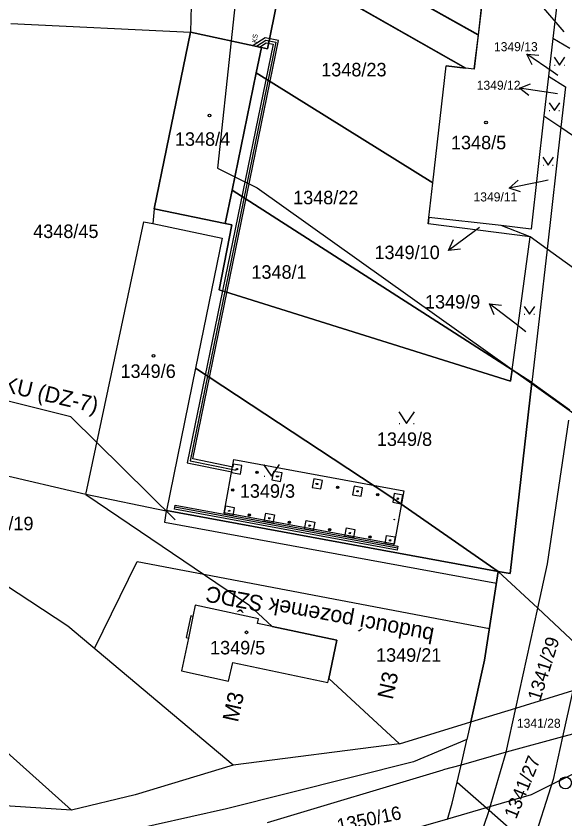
# Model space of a CAD drawing. Extents: x -735036 to -734743, y -1144813 to -1144181.
# Drawn here: x -734915.4 to -734846.3, y -1144707.5 to -1144606.3 of the extents above; entities that cross this region are included whole.
import ezdxf

# ---------------------------------------------------------------- set-up
doc = ezdxf.new("R2010")
doc.units = 0
for name, color, linetype in [('A3_ODVODŇOVACÍ ŽLAB', 7, 'Continuous'), ('A3_SIT_OBJEKT_N', 7, 'Continuous'), ('A3_SIT_OBJEKTY_N01', 7, 'Continuous'), ('BPEJ', 7, 'Continuous'), ('CKEL_VEDENI_NN_PODZ_N', 7, 'Continuous'), ('CKTEXTY_MALE', 7, 'Continuous'), ('hranice pl. určené SŽDC', 7, 'Continuous'), ('Katastr_HRANICE DRÁHY', 7, 'Continuous'), ('Katastr_Hranice parcel', 7, 'Continuous'), ('Katastr_Parcelní čísla', 7, 'Continuous'), ('Katastr_pozemek SŽDC_šrafy', 7, 'Continuous'), ('Katastr_pozemek_ČD_šrafy', 7, 'Continuous'), ('Katastr_Slučkované čáry', 7, 'Continuous'), ('Katastr_Značky kultur', 7, 'Continuous'), ('ZÁBORY_dočasné', 7, 'Continuous'), ('ZÁBORY_dočasné_šrafy', 7, 'Continuous')]:
    doc.layers.add(name, color=color, linetype=linetype)

msp = doc.modelspace()

# ---------------------------------------------------------------- linework, layer by layer
at = {"layer": 'A3_ODVODŇOVACÍ ŽLAB'}
msp.add_line((-734867.33, -1144673.4), (-734895.36, -1144668.25), dxfattribs=at)
at = {"layer": 'A3_SIT_OBJEKT_N'}
for p, q in [((-734895.42, -1144668.49), (-734895.31, -1144668)), ((-734867.38, -1144673.65), (-734895.42, -1144668.49)), ((-734895.31, -1144668), (-734867.29, -1144673.15)), ((-734867.29, -1144673.15), (-734867.38, -1144673.65))]:
    msp.add_line(p, q, dxfattribs=at)
at = {"layer": 'A3_SIT_OBJEKTY_N01'}
for p, q in [((-734887.65, -1144663.5), (-734887.62, -1144663.35)), ((-734887.5, -1144663.53), (-734887.65, -1144663.5)), ((-734887.62, -1144663.35), (-734887.48, -1144663.38)), ((-734887.48, -1144663.38), (-734887.5, -1144663.53)), ((-734885.06, -1144663.88), (-734885.05, -1144663.83)), ((-734885, -1144663.9), (-734885.06, -1144663.88)), ((-734885.05, -1144663.83), (-734884.99, -1144663.84)), ((-734884.99, -1144663.84), (-734885, -1144663.9)), ((-734882.59, -1144664.43), (-734882.56, -1144664.28)), ((-734882.44, -1144664.46), (-734882.59, -1144664.43)), ((-734882.56, -1144664.28), (-734882.31, -1144664.33)), ((-734882.43, -1144664.41), (-734882.44, -1144664.46)), ((-734882.33, -1144664.43), (-734882.43, -1144664.41)), ((-734882.31, -1144664.33), (-734882.33, -1144664.43)), ((-734877.61, -1144665.29), (-734877.59, -1144665.2)), ((-734877.51, -1144665.31), (-734877.61, -1144665.29)), ((-734877.59, -1144665.2), (-734877.35, -1144665.24)), ((-734877.52, -1144665.36), (-734877.51, -1144665.31)), ((-734877.37, -1144665.39), (-734877.52, -1144665.36)), ((-734877.35, -1144665.24), (-734877.37, -1144665.39)), ((-734874.93, -1144665.75), (-734874.92, -1144665.69)), ((-734874.92, -1144665.69), (-734874.86, -1144665.7)), ((-734874.86, -1144665.7), (-734874.87, -1144665.76)), ((-734888.13, -1144666.09), (-734888.12, -1144666.03)), ((-734888.07, -1144666.1), (-734888.13, -1144666.09)), ((-734888.12, -1144666.03), (-734888.06, -1144666.04)), ((-734888.06, -1144666.04), (-734888.07, -1144666.1)), ((-734874.87, -1144665.76), (-734874.93, -1144665.75)), ((-734872.46, -1144666.29), (-734872.43, -1144666.15)), ((-734872.31, -1144666.32), (-734872.46, -1144666.29)), ((-734872.43, -1144666.15), (-734872.28, -1144666.17)), ((-734872.28, -1144666.17), (-734872.31, -1144666.32)), ((-734869.86, -1144666.68), (-734869.85, -1144666.62)), ((-734869.8, -1144666.69), (-734869.86, -1144666.68)), ((-734869.85, -1144666.62), (-734869.79, -1144666.63)), ((-734869.79, -1144666.63), (-734869.8, -1144666.69)), ((-734867.39, -1144667.22), (-734867.36, -1144667.08)), ((-734867.24, -1144667.25), (-734867.39, -1144667.22)), ((-734867.36, -1144667.08), (-734867.22, -1144667.1)), ((-734867.22, -1144667.1), (-734867.24, -1144667.25)), ((-734888.62, -1144668.76), (-734888.59, -1144668.61)), ((-734888.59, -1144668.61), (-734888.44, -1144668.64)), ((-734888.44, -1144668.64), (-734888.47, -1144668.79)), ((-734888.47, -1144668.79), (-734888.62, -1144668.76)), ((-734886.04, -1144669.24), (-734886.03, -1144669.18)), ((-734885.98, -1144669.25), (-734886.04, -1144669.24)), ((-734886.03, -1144669.18), (-734885.97, -1144669.19)), ((-734885.97, -1144669.19), (-734885.98, -1144669.25)), ((-734883.55, -1144669.69), (-734883.53, -1144669.55)), ((-734883.41, -1144669.72), (-734883.55, -1144669.69)), ((-734883.53, -1144669.55), (-734883.38, -1144669.57)), ((-734883.38, -1144669.57), (-734883.41, -1144669.72)), ((-734880.98, -1144670.17), (-734880.97, -1144670.11)), ((-734880.92, -1144670.18), (-734880.98, -1144670.17)), ((-734880.97, -1144670.11), (-734880.91, -1144670.12)), ((-734880.91, -1144670.12), (-734880.92, -1144670.18)), ((-734878.49, -1144670.62), (-734878.46, -1144670.48)), ((-734878.34, -1144670.65), (-734878.49, -1144670.62)), ((-734878.46, -1144670.48), (-734878.31, -1144670.5)), ((-734878.31, -1144670.5), (-734878.34, -1144670.65)), ((-734867.78, -1144669.83), (-734867.77, -1144669.77)), ((-734867.72, -1144669.84), (-734867.78, -1144669.83)), ((-734867.77, -1144669.77), (-734867.71, -1144669.78)), ((-734867.71, -1144669.78), (-734867.72, -1144669.84)), ((-734875.91, -1144671.1), (-734875.9, -1144671.04)), ((-734875.85, -1144671.11), (-734875.91, -1144671.1)), ((-734875.9, -1144671.04), (-734875.84, -1144671.05)), ((-734875.84, -1144671.05), (-734875.85, -1144671.11)), ((-734873.42, -1144671.56), (-734873.4, -1144671.41)), ((-734873.28, -1144671.58), (-734873.42, -1144671.56)), ((-734873.4, -1144671.41), (-734873.25, -1144671.43)), ((-734873.25, -1144671.43), (-734873.28, -1144671.58)), ((-734870.85, -1144672.03), (-734870.84, -1144671.97)), ((-734870.79, -1144672.04), (-734870.85, -1144672.03)), ((-734870.84, -1144671.97), (-734870.78, -1144671.98)), ((-734870.78, -1144671.98), (-734870.79, -1144672.04)), ((-734868.36, -1144672.49), (-734868.33, -1144672.34)), ((-734868.21, -1144672.51), (-734868.36, -1144672.49)), ((-734868.33, -1144672.34), (-734868.18, -1144672.37)), ((-734868.18, -1144672.37), (-734868.21, -1144672.51))]:
    msp.add_line(p, q, dxfattribs=at)
for points in [[(-734888.19, -1144663.78), (-734888.21, -1144663.88), (-734887.12, -1144664.08), (-734886.92, -1144663), (-734888.01, -1144662.8), (-734888.08, -1144663.19), (-734893.11, -1144662.16), (-734882.3, -1144609.42), (-734883.98, -1144609.08), (-734885.53, -1144610.07), (-734884.7, -1144610.25), (-734883.87, -1144609.71), (-734883.01, -1144609.89), (-734893.81, -1144662.63)], [(-734889.17, -1144668.97), (-734887.93, -1144662.23), (-734866.54, -1144666.16), (-734867.77, -1144672.9)], [(-734882.94, -1144663.73), (-734883.14, -1144664.81), (-734882.06, -1144665.01), (-734881.86, -1144663.93)], [(-734877.88, -1144664.66), (-734878.07, -1144665.74), (-734876.99, -1144665.94), (-734876.79, -1144664.86)], [(-734872.81, -1144665.59), (-734873.01, -1144666.67), (-734871.93, -1144666.87), (-734871.73, -1144665.79)], [(-734867.75, -1144666.52), (-734867.94, -1144667.61), (-734866.86, -1144667.8), (-734866.66, -1144666.72)], [(-734889.17, -1144669.13), (-734888.97, -1144668.06), (-734887.89, -1144668.26), (-734888.09, -1144669.33)], [(-734884.11, -1144670.06), (-734883.91, -1144668.99), (-734882.83, -1144669.19), (-734883.02, -1144670.26)], [(-734879.04, -1144670.99), (-734878.84, -1144669.92), (-734877.76, -1144670.12), (-734877.96, -1144671.19)], [(-734873.98, -1144671.93), (-734873.78, -1144670.85), (-734872.7, -1144671.05), (-734872.89, -1144672.12)], [(-734868.91, -1144672.86), (-734868.71, -1144671.79), (-734867.63, -1144671.98), (-734867.83, -1144673.06)]]:
    msp.add_lwpolyline(points, close=True, dxfattribs=at)
for centre in [(-734885.02, -1144663.86), (-734874.89, -1144665.72), (-734888.09, -1144666.06), (-734869.83, -1144666.65), (-734886.01, -1144669.21), (-734880.94, -1144670.14), (-734875.88, -1144671.07), (-734870.81, -1144672)]:
    msp.add_circle(centre, 0.15, dxfattribs=at)
at = {"layer": 'BPEJ'}
for points in [[(-734886.95, -1144596.85), (-734888.29, -1144609.47), (-734890, -1144625.5), (-734887.82, -1144626.59), (-734885, -1144628), (-734852.91, -1144650.88), (-734852.15, -1144651.42), (-734850.43, -1144652.65), (-734834.73, -1144663.85), (-734834.99, -1144666), (-734826.29, -1144672.48), (-734825.67, -1144670.31), (-734820.68, -1144673.87), (-734820.5, -1144674), (-734820.82, -1144674.78), (-734818.52, -1144675.9), (-734816.23, -1144677.02), (-734810.97, -1144679.57), (-734807.09, -1144681.45), (-734806.63, -1144681.68), (-734805.5, -1144680.5), (-734802.5, -1144683.25), (-734799.5, -1144686)], [(-734875.41, -1144811.46), (-734872.9, -1144805.78), (-734867.89, -1144794.43), (-734854.34, -1144763.72), (-734850.2, -1144754.32), (-734842.33, -1144736.48), (-734836.55, -1144723.38), (-734836.47, -1144723.21), (-734828.55, -1144705.26), (-734828.47, -1144705.07), (-734837.14, -1144702.69), (-734834.01, -1144696), (-734841.2, -1144699.67), (-734841.55, -1144701.48), (-734843.42, -1144700.96), (-734850.5, -1144704.5), (-734856.16, -1144706.13), (-734861.05, -1144707.56), (-734878.02, -1144712.44), (-734888.06, -1144715.34), (-734896.33, -1144716.95), (-734914.06, -1144720.39), (-734915.89, -1144720.74)]]:
    msp.add_lwpolyline(points, dxfattribs=at)
at = {"layer": 'CKEL_VEDENI_NN_PODZ_N'}
msp.add_lwpolyline([(-734885.11, -1144610.16), (-734883.92, -1144609.39), (-734882.65, -1144609.66), (-734893.46, -1144662.4), (-734887.67, -1144663.58)], dxfattribs=at)
at = {"layer": 'hranice pl. určené SŽDC'}
for p, q in [((-734905.48, -1144686.06), (-734900.12, -1144675.07)), ((-734900.12, -1144675.07), (-734855.78, -1144683.52))]:
    msp.add_line(p, q, dxfattribs=at)
at = {"layer": 'Katastr_HRANICE DRÁHY'}
for p, q in [((-734906.57, -1144666.66), (-734899.28, -1144632.27)), ((-734906.57, -1144666.66), (-734930.18, -1144661.14)), ((-734867.09, -1144698.06), (-734888.03, -1144700.76))]:
    msp.add_line(p, q, dxfattribs=at)
for points in [[(-734893.32, -1144605), (-734893.39, -1144608.37)], [(-734896.4, -1144623.07), (-734893.39, -1144608.37)], [(-734846.19, -1144615.27), (-734846.77, -1144620.37)], [(-734846.77, -1144620.37), (-734848.51, -1144635.73)], [(-734897.96, -1144630.65), (-734896.4, -1144623.07)], [(-734897.96, -1144630.65), (-734898.12, -1144632.51)], [(-734899.28, -1144632.27), (-734898.12, -1144632.51)], [(-734848.51, -1144635.73), (-734850.42, -1144652.54)], [(-734850.42, -1144652.54), (-734853.15, -1144676.61)], [(-734908.82, -1144683.24), (-734932.55, -1144667.65)], [(-734854.65, -1144676.33), (-734856.41, -1144687.5)], [(-734853.15, -1144676.61), (-734854.65, -1144676.33)], [(-734888.03, -1144700.76), (-734908.82, -1144683.24)], [(-734856.41, -1144687.5), (-734858.12, -1144695.3)], [(-734867.09, -1144698.06), (-734858.12, -1144695.3)]]:
    msp.add_lwpolyline(points, dxfattribs=at)
at = {"layer": 'Katastr_Hranice parcel'}
for points in [[(-734857.17, -1144608.74), (-734880.66, -1144595.58)], [(-734883.7, -1144610.47), (-734881.55, -1144599.93)], [(-734881.55, -1144599.93), (-734858.79, -1144612.91)], [(-734846.8, -1144600.6), (-734847.79, -1144609.19)], [(-734856.63, -1144604.15), (-734857.17, -1144608.74)], [(-734916.03, -1144607.28), (-734893.39, -1144608.37)], [(-734893.39, -1144608.37), (-734884.47, -1144610.3)], [(-734857.17, -1144608.74), (-734857.68, -1144613.04)], [(-734847.79, -1144609.19), (-734848.33, -1144613.91)], [(-734845.64, -1144610.44), (-734847.79, -1144609.19)], [(-734885.13, -1144613.52), (-734884.47, -1144610.3)], [(-734884.47, -1144610.3), (-734883.7, -1144610.47)], [(-734862.9, -1144627.38), (-734861.22, -1144612.64)], [(-734858.79, -1144612.91), (-734861.22, -1144612.64)], [(-734857.68, -1144613.04), (-734858.79, -1144612.91)], [(-734888.17, -1144628.27), (-734885.13, -1144613.52)], [(-734885.13, -1144613.52), (-734862.9, -1144627.38)], [(-734848.33, -1144613.91), (-734848.9, -1144618.91)], [(-734848.33, -1144613.91), (-734846.19, -1144615.27)], [(-734848.9, -1144618.91), (-734850.53, -1144633.19)], [(-734848.9, -1144618.91), (-734846.77, -1144620.37)], [(-734846.77, -1144620.37), (-734841.89, -1144623.71)], [(-734889.04, -1144632.49), (-734888.17, -1144628.27)], [(-734888.17, -1144628.27), (-734852.92, -1144650.93)], [(-734863.4, -1144631.72), (-734862.9, -1144627.38)], [(-734889.04, -1144632.49), (-734897.96, -1144630.65)], [(-734863.4, -1144631.72), (-734863.49, -1144632.52)], [(-734854.28, -1144632.76), (-734863.4, -1144631.72)], [(-734898.12, -1144632.51), (-734889.41, -1144634.32)], [(-734889.81, -1144640.87), (-734888.21, -1144632.66)], [(-734888.21, -1144632.66), (-734889.04, -1144632.49)], [(-734850.65, -1144634.19), (-734863.49, -1144632.52)], [(-734850.53, -1144633.19), (-734854.28, -1144632.76)], [(-734850.65, -1144634.19), (-734854.28, -1144632.76)], [(-734889.41, -1144634.32), (-734892.76, -1144650.74)], [(-734852.92, -1144650.93), (-734850.65, -1144634.19)], [(-734848.51, -1144635.73), (-734850.65, -1144634.19)], [(-734843.69, -1144639.2), (-734848.51, -1144635.73)], [(-734853.11, -1144652.34), (-734889.81, -1144640.87)], [(-734892.76, -1144650.74), (-734896.42, -1144668.65)], [(-734892.76, -1144650.74), (-734868.44, -1144666.76)], [(-734852.92, -1144650.93), (-734853.11, -1144652.34)], [(-734852.92, -1144650.93), (-734850.42, -1144652.54)], [(-734850.42, -1144652.54), (-734845.63, -1144655.97)], [(-734896.45, -1144668.76), (-734906.57, -1144666.66)], [(-734906.57, -1144666.66), (-734886.07, -1144680.55)], [(-734854.65, -1144676.33), (-734868.44, -1144666.76)], [(-734896.42, -1144668.65), (-734896.45, -1144668.76)], [(-734854.65, -1144676.33), (-734896.42, -1144668.65)], [(-734849.69, -1144680.98), (-734854.65, -1144676.33)], [(-734892.81, -1144680.6), (-734893.1, -1144682)], [(-734884.85, -1144682.29), (-734892.81, -1144680.6)], [(-734886.07, -1144680.55), (-734883.11, -1144683.28)], [(-734844.19, -1144686.14), (-734849.69, -1144680.98)], [(-734908.39, -1144706.42), (-734935.61, -1144682)], [(-734893.37, -1144681.94), (-734893.96, -1144684.67)], [(-734893.1, -1144682), (-734893.37, -1144681.94)], [(-734884.98, -1144682.88), (-734884.85, -1144682.29)], [(-734883.11, -1144683.28), (-734884.98, -1144682.88)], [(-734874.98, -1144685.01), (-734883.11, -1144683.28)], [(-734893.67, -1144684.73), (-734894.55, -1144688.88)], [(-734893.96, -1144684.67), (-734893.67, -1144684.73)], [(-734876, -1144689.84), (-734874.98, -1144685.01)], [(-734888.61, -1144690.15), (-734888.09, -1144687.8)], [(-734888.09, -1144687.8), (-734876.11, -1144690.34)], [(-734894.55, -1144688.88), (-734888.61, -1144690.15)], [(-734876.11, -1144690.34), (-734876, -1144689.84)], [(-734876, -1144689.84), (-734867.09, -1144698.06)], [(-734852.46, -1144693.56), (-734845.28, -1144691.36)], [(-734858.12, -1144695.3), (-734852.46, -1144693.56)], [(-734858.12, -1144695.3), (-734858.6, -1144697.51)], [(-734840.41, -1144695.55), (-734846.56, -1144697.19)], [(-734858.6, -1144697.51), (-734865.34, -1144700.35)], [(-734859.34, -1144700.73), (-734858.65, -1144697.78)], [(-734858.65, -1144697.78), (-734858.6, -1144697.51)], [(-734846.56, -1144697.19), (-734853.68, -1144699.09)], [(-734853.68, -1144699.09), (-734859.34, -1144700.73)], [(-734888.03, -1144700.76), (-734900.37, -1144704.49)], [(-734865.34, -1144700.35), (-734888.87, -1144706.25)], [(-734859.34, -1144700.73), (-734861.61, -1144701.35)], [(-734859.84, -1144702.9), (-734859.34, -1144700.73)], [(-734883.72, -1144707.99), (-734861.61, -1144701.35)], [(-734860.46, -1144705.55), (-734859.84, -1144702.9)], [(-734859.84, -1144702.9), (-734855.82, -1144706.43)], [(-734908.39, -1144706.42), (-734927.72, -1144705.17)], [(-734900.37, -1144704.49), (-734908.39, -1144706.42)], [(-734861.06, -1144707.58), (-734860.46, -1144705.55)], [(-734888.87, -1144706.25), (-734902.35, -1144709.26)], [(-734855.82, -1144706.43), (-734850.48, -1144711.13)]]:
    msp.add_lwpolyline(points, dxfattribs=at)
at = {"layer": 'Katastr_Parcelní čísla'}
for p, q in [((-734846.36, -1144608.35), (-734847.12, -1144607.47)), ((-734850.4, -1144612.5), (-734851.04, -1144611.14)), ((-734847.15, -1144613.85), (-734847.76, -1144613.43)), ((-734850.82, -1144616.36), (-734852, -1144615.43)), ((-734847.22, -1144616.14), (-734848.04, -1144616.02)), ((-734848.37, -1144627.04), (-734849.36, -1144627.24)), ((-734851.86, -1144628.51), (-734853.28, -1144628.03)), ((-734857.03, -1144632.99), (-734857.7, -1144633.49)), ((-734859.42, -1144635.71), (-734860.91, -1144635.88)), ((-734855.17, -1144643.99), (-734855.74, -1144642.6)), ((-734851.17, -1144646.14), (-734852.58, -1144645.05))]:
    msp.add_line(p, q, dxfattribs=at)
for points in [[(-734847.12, -1144607.47), (-734849.73, -1144604.44), (-734848.32, -1144604.94)], [(-734847.76, -1144613.43), (-734851.04, -1144611.14), (-734849.55, -1144611.27)], [(-734848.04, -1144616.02), (-734852, -1144615.43), (-734850.6, -1144614.88)], [(-734849.36, -1144627.24), (-734853.28, -1144628.03), (-734852.15, -1144627.04)], [(-734857.7, -1144633.49), (-734860.91, -1144635.88), (-734860.31, -1144634.5)], [(-734852.58, -1144645.05), (-734855.74, -1144642.6), (-734854.25, -1144642.8)]]:
    msp.add_lwpolyline(points, dxfattribs=at)
at = {"layer": 'Katastr_pozemek SŽDC_šrafy'}
for points in [[(-734879.81, -1144591.4), (-734880.65, -1144595.54), (-734857.16, -1144608.7), (-734856.62, -1144604.11), (-734879.81, -1144591.4)], [(-734881.55, -1144599.93), (-734891.82, -1144594.07), (-734893.32, -1144605), (-734893.39, -1144608.37), (-734884.47, -1144610.3), (-734883.7, -1144610.47), (-734881.55, -1144599.93)], [(-734880.65, -1144595.54), (-734881.54, -1144599.89), (-734858.78, -1144612.87), (-734857.67, -1144613), (-734857.16, -1144608.7), (-734880.65, -1144595.54)], [(-734881.55, -1144599.93), (-734883.7, -1144610.47), (-734884.47, -1144610.3), (-734885.13, -1144613.52), (-734862.9, -1144627.38), (-734861.22, -1144612.64), (-734858.79, -1144612.91), (-734881.55, -1144599.93)], [(-734885.13, -1144613.52), (-734884.47, -1144610.3), (-734893.39, -1144608.37), (-734896.4, -1144623.07), (-734897.96, -1144630.65), (-734889.04, -1144632.49), (-734888.17, -1144628.27), (-734885.13, -1144613.52)], [(-734862.9, -1144627.38), (-734885.13, -1144613.52), (-734888.17, -1144628.27), (-734852.92, -1144650.93), (-734850.65, -1144634.19), (-734863.49, -1144632.52), (-734863.4, -1144631.72), (-734862.9, -1144627.38)], [(-734888.17, -1144628.27), (-734889.04, -1144632.49), (-734888.21, -1144632.66), (-734889.81, -1144640.87), (-734853.11, -1144652.34), (-734852.92, -1144650.93), (-734888.17, -1144628.27)], [(-734850.42, -1144652.54), (-734852.92, -1144650.93), (-734853.11, -1144652.34), (-734889.81, -1144640.87), (-734888.21, -1144632.66), (-734889.04, -1144632.49), (-734897.96, -1144630.65), (-734898.12, -1144632.51), (-734889.41, -1144634.32), (-734892.76, -1144650.74), (-734868.44, -1144666.76), (-734854.65, -1144676.33), (-734853.15, -1144676.61), (-734850.42, -1144652.54)], [(-734892.76, -1144650.74), (-734896.42, -1144668.65), (-734854.65, -1144676.33), (-734868.44, -1144666.76), (-734892.76, -1144650.74)]]:
    msp.add_lwpolyline(points, dxfattribs=at)
at = {"layer": 'Katastr_pozemek_ČD_šrafy'}
for p, q in [((-734896.45, -1144668.76), (-734906.57, -1144666.66)), ((-734906.57, -1144666.66), (-734886.07, -1144680.55)), ((-734896.42, -1144668.65), (-734896.45, -1144668.76)), ((-734854.65, -1144676.33), (-734896.42, -1144668.65)), ((-734856.41, -1144687.5), (-734854.65, -1144676.33)), ((-734886.07, -1144680.55), (-734883.11, -1144683.28)), ((-734883.11, -1144683.28), (-734874.98, -1144685.01)), ((-734874.98, -1144685.01), (-734876, -1144689.84)), ((-734858.12, -1144695.3), (-734856.41, -1144687.5)), ((-734876, -1144689.84), (-734867.09, -1144698.06)), ((-734867.09, -1144698.06), (-734858.12, -1144695.3))]:
    msp.add_line(p, q, dxfattribs=at)
at = {"layer": 'Katastr_Slučkované čáry'}
for points in [[(-734848.46, -1144675.36), (-734845.78, -1144657.26)], [(-734849.69, -1144680.98), (-734848.46, -1144675.36)], [(-734852.46, -1144693.56), (-734849.69, -1144680.98)], [(-734893.1, -1144682), (-734893.67, -1144684.73)], [(-734845.28, -1144691.36), (-734846.56, -1144697.19)], [(-734853.68, -1144699.09), (-734852.46, -1144693.56)], [(-734846.56, -1144697.19), (-734847.73, -1144702.54)], [(-734855.82, -1144706.43), (-734853.68, -1144699.09)], [(-734847.73, -1144702.54), (-734850.48, -1144711.13)], [(-734859.82, -1144718.19), (-734855.94, -1144706.83)], [(-734855.94, -1144706.83), (-734855.82, -1144706.43)]]:
    msp.add_lwpolyline(points, dxfattribs=at)
at = {"layer": 'Katastr_Značky kultur'}
for p, q in [((-734847.61, -1144611.55), (-734846.94, -1144612.55)), ((-734846.94, -1144612.55), (-734846.27, -1144611.55)), ((-734847.58, -1144612.55), (-734847.51, -1144612.55)), ((-734846.37, -1144612.55), (-734846.3, -1144612.55)), ((-734848.26, -1144617.27), (-734847.59, -1144618.27)), ((-734847.59, -1144618.27), (-734846.92, -1144617.27)), ((-734848.23, -1144618.27), (-734848.16, -1144618.27)), ((-734847.02, -1144618.27), (-734846.95, -1144618.27)), ((-734849.05, -1144624.13), (-734848.38, -1144625.13)), ((-734848.38, -1144625.13), (-734847.71, -1144624.13)), ((-734849.02, -1144625.13), (-734848.95, -1144625.13)), ((-734847.81, -1144625.13), (-734847.74, -1144625.13)), ((-734851.41, -1144642.93), (-734850.74, -1144643.93)), ((-734850.74, -1144643.93), (-734850.07, -1144642.93)), ((-734851.38, -1144643.93), (-734851.31, -1144643.93)), ((-734850.17, -1144643.93), (-734850.1, -1144643.93)), ((-734867.14, -1144657.71), (-734867.04, -1144657.71)), ((-734865.34, -1144657.71), (-734865.24, -1144657.71)), ((-734884.14, -1144664.35), (-734884.04, -1144664.35)), ((-734882.34, -1144664.35), (-734882.24, -1144664.35))]:
    msp.add_line(p, q, dxfattribs=at)
for points in [[(-734867.19, -1144656.21), (-734866.19, -1144657.71), (-734865.19, -1144656.21)], [(-734884.19, -1144662.85), (-734883.19, -1144664.35), (-734882.19, -1144662.85)]]:
    msp.add_lwpolyline(points, dxfattribs=at)
for centre, radius in [((-734891.01, -1144618.89), 0.175), ((-734856.2, -1144619.77), 0.175), ((-734898.05, -1144649.17), 0.175), ((-734886.34, -1144684.01), 0.175), ((-734846.21, -1144702.98), 0.756)]:
    msp.add_circle(centre, radius, dxfattribs=at)
at = {"layer": 'ZÁBORY_dočasné'}
for p, q in [((-734908.46, -1144656.86), (-734949.49, -1144646.65)), ((-734908.46, -1144656.86), (-734895.31, -1144669.83)), ((-734896.42, -1144668.65), (-734896.45, -1144668.76)), ((-734854.65, -1144676.33), (-734896.42, -1144668.65)), ((-734896.45, -1144668.76), (-734896.69, -1144670.13)), ((-734896.69, -1144670.13), (-734854.88, -1144677.82)), ((-734854.88, -1144677.82), (-734854.65, -1144676.33))]:
    msp.add_line(p, q, dxfattribs=at)
at = {"layer": 'ZÁBORY_dočasné_šrafy'}
msp.add_lwpolyline([(-734896.42, -1144668.65), (-734896.45, -1144668.76), (-734896.69, -1144670.13), (-734854.88, -1144677.82), (-734854.65, -1144676.33), (-734896.42, -1144668.65)], dxfattribs=at)

# ---------------------------------------------------------------- texts
at = {"layer": 'CKTEXTY_MALE'}
msp.add_text('KS', height=0.6, rotation=83.326, dxfattribs=at).set_placement((-734885.06, -1144609.75))
at = {"layer": 'hranice pl. určené SŽDC'}
for s, rotation, p in [('budoucí pozemek SŽDC', 169.4202, (-734862.62, -1144683.49)), ('N3', 77.5575, (-734867.95, -1144692.57)), ('M3', 77.5575, (-734887.44, -1144695.42))]:
    msp.add_text(s, height=2, rotation=rotation, dxfattribs=at).set_placement(p)
at = {"layer": 'Katastr_Parcelní čísla'}
for s, height, p in [('1349/13', 1.14, (-734855.2, -1144610.78)), ('1348/23', 1.7, (-734876.94, -1144613.95)), ('1349/12', 1.14, (-734857.37, -1144615.64)), ('1348/4', 1.7, (-734895.36, -1144622.7)), ('1348/5', 1.7, (-734860.61, -1144623.14)), ('1348/22', 1.7, (-734880.48, -1144630.07)), ('1349/11', 1.14, (-734857.77, -1144629.71)), ('4348/45', 1.7, (-734913.2, -1144634.32)), ('1349/10', 1.7, (-734870.24, -1144636.98)), ('1348/1', 1.7, (-734885.73, -1144639.45)), ('1349/9', 1.7, (-734863.88, -1144643.21)), ('1349/6', 1.7, (-734902.21, -1144651.95)), ('1349/8', 1.7, (-734869.94, -1144660.52)), ('1349/3', 1.7, (-734887.19, -1144667.05)), ('1349/19', 1.7, (-734921.38, -1144671.15)), ('1349/5', 1.7, (-734890.94, -1144686.79)), ('1349/21', 1.7, (-734870.04, -1144687.72)), ('1341/28', 1.14, (-734852.31, -1144696.04))]:
    msp.add_text(s, height=height, dxfattribs=at).set_placement(p)
for s, rotation, p in [('1341/29', 72.6424, (-734849.38, -1144692.76)), ('1341/27', 67.7765, (-734852.41, -1144707.63)), ('1350/16', 11.9909, (-734874.77, -1144709.23))]:
    msp.add_text(s, height=1.7, rotation=rotation, dxfattribs=at).set_placement(p)
at = {"layer": 'ZÁBORY_dočasné'}
msp.add_text('DOČASNÝ ZÁBOR POZEMKU (DZ-7)', height=2, rotation=346.8377, dxfattribs=at).set_placement((-734949.69, -1144646.02))

doc.saveas('drawing.dxf')
